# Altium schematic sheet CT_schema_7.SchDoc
size 277 x 170 mm
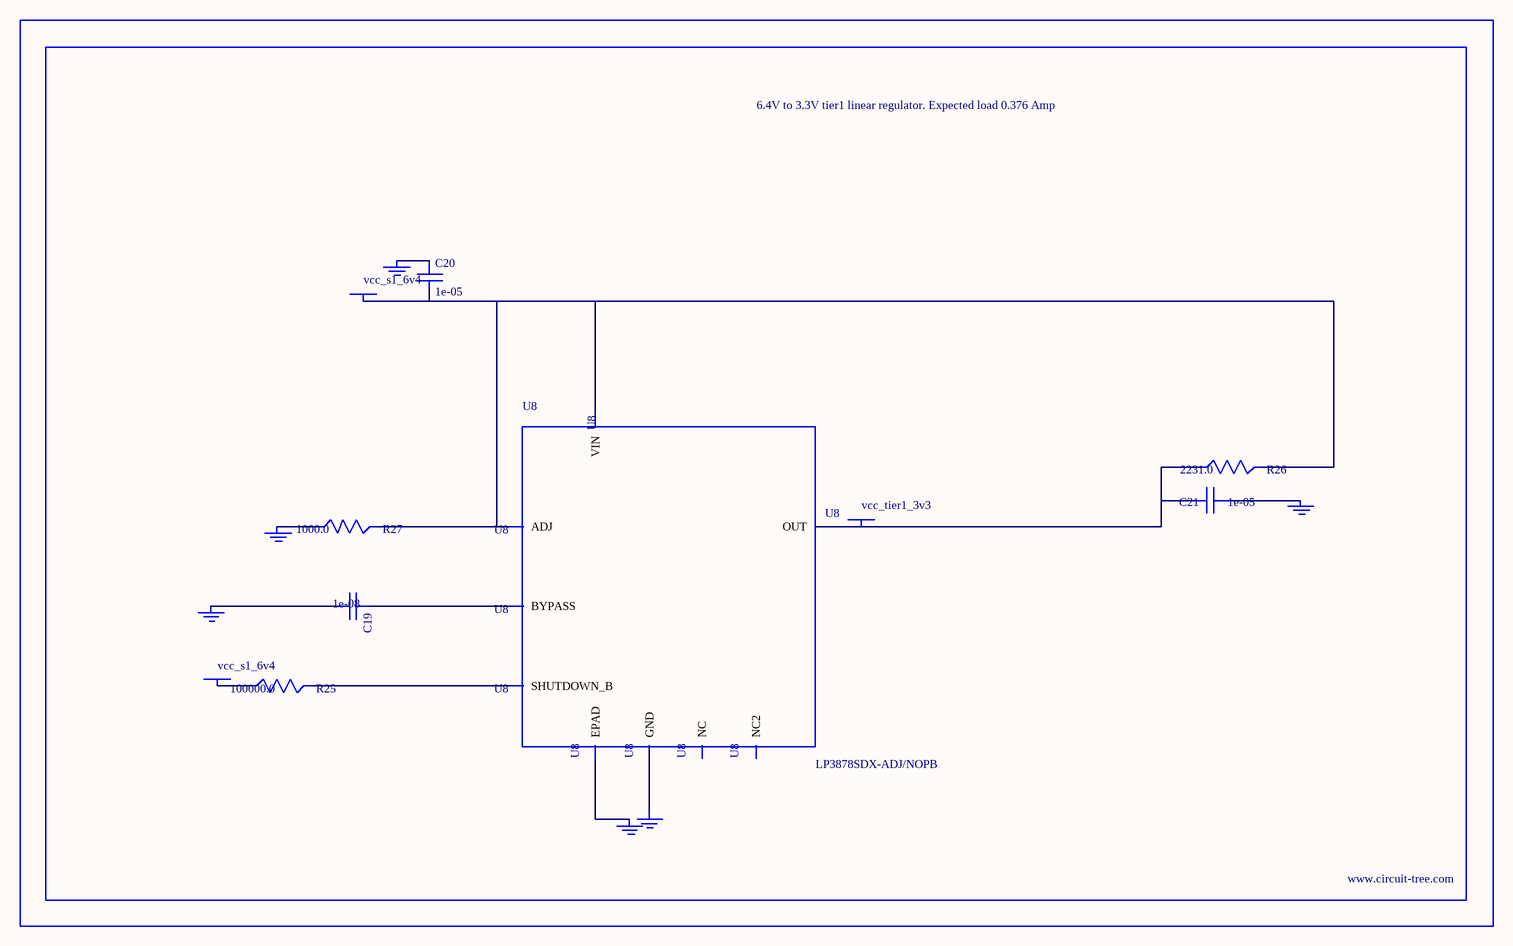
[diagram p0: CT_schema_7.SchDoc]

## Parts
BORDER6  (no value)
C19  1e-08  [C0402]
C20  1e-05  [C1206]
C21  1e-05  [C1210]
GND_INSTANCE_6_0  (no value)
GND_INSTANCE_6_1  (no value)
GND_INSTANCE_6_2  (no value)
GND_INSTANCE_6_3  (no value)
GND_INSTANCE_6_4  (no value)
GND_INSTANCE_6_5  (no value)
POWER_INSTANCE_6_0  vcc_s1_6v4
POWER_INSTANCE_6_1  vcc_s1_6v4
POWER_INSTANCE_6_2  vcc_tier1_3v3
R25  100000.0  [R0603]
R26  2231.0  [R0603]
R27  1000.0  [R0603]
U8  LP3878SDX-ADJ/NOPB  [WSON-8]

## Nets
NetC19_1: C19.1 U8.1(BYPASS)
NetC19_2: C19.2 GND_INSTANCE_6_0.0(GND)
NetC20_1: C20.1 GND_INSTANCE_6_1.0(GND)
NetC20_2: C20.2 POWER_INSTANCE_6_0.0(PWR) R26.2 R27.2 U8.4(VIN) U8.6(ADJ)
NetC21_1: C21.1 GND_INSTANCE_6_2.0(GND)
NetC21_2: C21.2 POWER_INSTANCE_6_2.0(PWR) R26.1 U8.5(OUT)
NetGND_INSTANCE_6_3_0: GND_INSTANCE_6_3.0(GND) R27.1
NetGND_INSTANCE_6_4_0: GND_INSTANCE_6_4.0(GND) U8.PAD(EPAD)
NetGND_INSTANCE_6_5_0: GND_INSTANCE_6_5.0(GND) U8.3(GND)
NetPOWER_INSTANCE_6_1_0: POWER_INSTANCE_6_1.0(PWR) R25.1
NetR25_2: R25.2 U8.8(SHUTDOWN_B)

Not connected (* = marked no-connect by the designer): U8 2(NC) 7(NC2)

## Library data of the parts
BORDER6 = BORDER_PAGE6
C19 = C0402C103K3RAC
C20 = C1206C106K3RACTU
C21 = GRM32DR61E106MA12L
GND_INSTANCE_6_0-GND_INSTANCE_6_5 = GND
POWER_INSTANCE_6_0-POWER_INSTANCE_6_2 = PWR
R25 = RC0603JR-07100KL
R26 = R26
R27 = RC0603JR-071KL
